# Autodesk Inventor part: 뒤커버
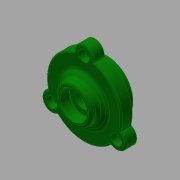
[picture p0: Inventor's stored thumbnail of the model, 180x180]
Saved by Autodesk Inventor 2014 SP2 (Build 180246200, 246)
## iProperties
Created: 2016-05
Part Number: 뒤커버
Document SubType Name: Modeling
Designer: mduedu
Density: 2.71 g/cm^3
Material: 알루미늄 6061
Appearance: 진녹색
Author: mduedu
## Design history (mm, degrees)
sketch "스케치1"
  geometry: C1 r 20 at (0, 0); C2 r 27.5 at (0, 0); 1 further point
  constraints: 2 centre point, 2 coincident
  dimensions: "d33" = 55 diameter of C2; "d34" = 40 diameter of C1
extrude "돌출1" new body sketch "스케치1" distance "d0" = 8; taper "d1" = 0 deg
extrude "돌출2" join sketch "스케치1" distance "d2" = 8; taper "d3" = 0 deg; dims "d35" = 9, "d36" = 0
sketch "스케치5"
  geometry: L1 (-27.5, 8)-(27.5, 8) reference; L2 (0, 0)-(0, 15); L3 (-27.5, 0)-(27.5, 0) reference; L4 (17.5, 8)-(0, 8); A1 r 25.375 centre (0, -10.375) between (17.5, 8) and (0, 15)
  constraints: 4 end point, 3 point on line, 2 point on circle, 1 centre point, 1 midpoint, 1 perpendicular
  dimensions: "d37" = 17.5 distance from line of L2 L4.start; "d39" = 7 distance from line of L1 L2.end
revolve "회전2" sketch "스케치5" stored, may be unused: angle "d40" = 90 deg
node "작업 평면1"
sketch "스케치6"
  geometry: C1 r 13.5 at (0, 0); 1 further point
  constraints: 1 centre point, 1 coincident
  dimensions: "d42" = 27 diameter of C1
extrude "돌출4" join sketch "스케치6" stored distance "d43" = 10; taper "d44" = 0 deg
sketch "스케치4"
  geometry: L1 (0, -9)-(0, 16); L2 (-15, -9)-(-15, 0); L3 (-15, 0)-(-10, 0); L4 (-10, 0)-(-10, 3); L5 (-10, 3)-(-6, 3); L6 (-6, 3)-(-6, 8.6); L7 (-6, 8.6)-(-10, 8.6); L8 (-10, 8.6)-(-10, 16); L9 (20, -9)-(-20, -9) reference; L10 (-13.5, 16)-(13.5, 16) reference; 1 further point
  constraints: 16 end point, 6 parallel, 3 point on line, 2 midpoint, 1 perpendicular, 1 vertical
  dimensions: "d15" = 30 diameter of L2 L1; "d16" = 20 diameter of L8 L1; "d18" = 9 distance of L2.start L2.end; "d19" = 3 distance of L3.end L4.end; "d20" = 20 diameter of L4 L1; "d21" = 12 diameter of L6 L1; "d45" = 7.4 distance of L7.end L8.end
revolve "회전1" sketch "스케치4" stored, may be unused: angle "d22" = 90 deg
fillet "모깎기2" dims "d23" = 3
fillet "모깎기3" dims "d24" = 0.3
chamfer "모따기2" distance "d46" = 1; stored, may be unused: second distance "d47" = 2, angle "d48" = 45 deg
fillet "모깎기4" dims "d49" = 3
fillet "모깎기5" dims "d50" = 2
sketch "스케치7"
  geometry: C1 r 7 at (0, 27.5); 2 further points
  constraints: 3 vertical alignment, 1 centre point, 2 other
  dimensions: "d54" = 14 diameter of C1
extrude "돌출5" join sketch "스케치7" stored distance "d55" = 10; taper "d56" = 0 deg
fillet "모깎기6" dims "d57" = 1
fillet "모깎기7" dims "d61" = 1
sketch "스케치8" dims "d62" = 55 (derived)
  geometry: C1 r 18.661 at (0, 0) reference; A1 r 2 centre (-7.999, 27.355) between (-7.437, 25.435) and (-5.999, 27.391) reference; A2 r 26.5 centre (0, 0) between (-7.437, 25.435) and (-25.746, -6.277) reference; A3 r 2 centre (-27.689, -6.75) between (-26.721, -8.5) and (-25.746, -6.277) reference; A4 r 6 centre (-23.816, -13.75) between (-26.721, -8.5) and (-20.722, -18.891) reference; A5 r 2 centre (-19.69, -20.604) between (-18.309, -19.158) and (-20.722, -18.891) reference; A6 r 26.5 centre (0, 0) between (-18.309, -19.158) and (18.309, -19.158) reference; A7 r 2 centre (19.69, -20.604) between (20.722, -18.891) and (18.309, -19.158) reference; A8 r 6 centre (23.816, -13.75) between (20.722, -18.891) and (26.721, -8.5) reference; A9 r 2 centre (27.689, -6.75) between (25.746, -6.277) and (26.721, -8.5) reference; A10 r 26.5 centre (0, 0) between (25.746, -6.277) and (7.437, 25.435) reference; A11 r 2 centre (7.999, 27.355) between (5.999, 27.391) and (7.437, 25.435) reference; A12 r 6 centre (0, 27.5) between (5.999, 27.391) and (-5.999, 27.391) reference; 4 further points
  constraints: 2 coincident, 1 vertical alignment, 6 other
  dimensions: "d65" = 360 deg dimension on A2.centre point (0, 27.5) (derived)
sketch "스케치9"
  geometry: 3 further points
  constraints: 3 other
hole "구멍2" sketch "스케치9" at (-23.816, -13.75), (23.816, -13.75), (0, 27.5) diameter "d67" = 4.5; stored, may be unused: countersink angle "d71" = 90 deg, drill point angle "d73" = 0 deg; dims "d68" = 6, "d69" = 8, "d70" = 4.6, "d72" = 8
chamfer "모따기3" distance "d76" = 0.7; stored, may be unused: second distance "d77" = 2, angle "d78" = 30 deg
node "솔리드1"
pattern_circular "원형 패턴1" dims angle "d59" = 360 deg
other parameters: "d41" = 8
